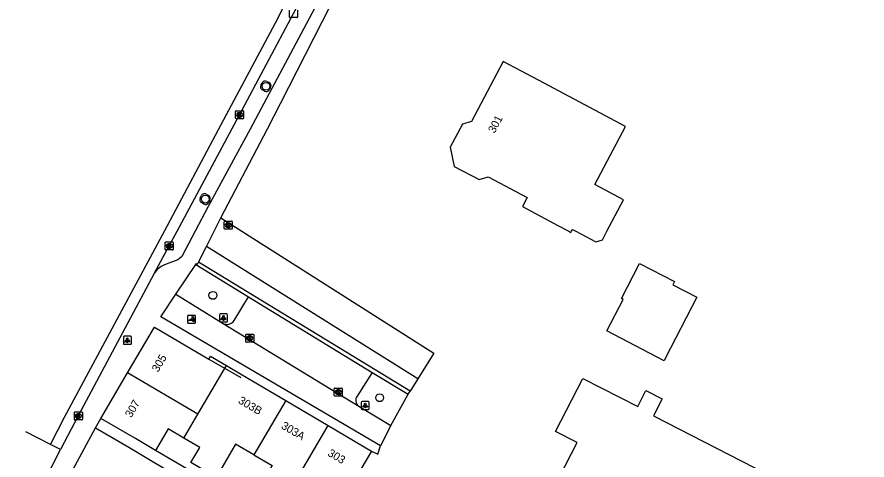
# Model space of a CAD drawing. Extents: x 160158 to 160921, y 381517 to 382041.
# Drawn here: x 160220.2 to 160326.4, y 381721.4 to 381776.8 of the extents above; entities that cross this region are included whole.
import ezdxf

# ---------------------------------------------------------------- set-up
doc = ezdxf.new("R2010")
doc.units = 0
for name, color, linetype in [('IMGEO_Boom', 7, 'Continuous'), ('IMGEO_Groenvoorziening', 7, 'Continuous'), ('IMGEO_Haag', 7, 'Continuous'), ('IMGEO_Kolk', 7, 'Continuous'), ('IMGEO_Lichtpunt', 7, 'Continuous'), ('IMGEO_Muur', 7, 'Continuous'), ('IMGEO_Pand', 7, 'Continuous'), ('IMGEO_Pand_nummerreeks', 7, 'Continuous'), ('IMGEO_Parkeervlak_halfverhard', 7, 'Continuous'), ('IMGEO_Parkeervlak_open', 7, 'Continuous'), ('IMGEO_Poller', 7, 'Continuous'), ('IMGEO_Rijbaan_lokaal_gesloten', 7, 'Continuous'), ('IMGEO_Rijbaan_lokaal_open', 7, 'Continuous'), ('IMGEO_Voetpad_open', 7, 'Continuous')]:
    doc.layers.add(name, color=color, linetype=linetype)

msp = doc.modelspace()

# ---------------------------------------------------------------- linework, layer by layer
at = {"layer": 'IMGEO_Boom'}
for centre in [(160251.32, 381768.11), (160243.74, 381754.01), (160244.69, 381741.97), (160265.53, 381729.18)]:
    msp.add_circle(centre, 0.489, dxfattribs=at)
at = {"layer": 'IMGEO_Groenvoorziening'}
msp.add_lwpolyline([(160266.92, 381725.7), (160269.08, 381729.64)], dxfattribs=at)
at = {"layer": 'IMGEO_Haag'}
for points in [[(160242.54, 381745.85), (160249.15, 381741.8)], [(160264.57, 381732.35), (160269.08, 381729.64)], [(160269.08, 381729.64), (160269.34, 381730.01)]]:
    msp.add_lwpolyline(points, dxfattribs=at)
at = {"layer": 'IMGEO_Kolk'}
for p, q in [((160254.24, 381776.77), (160254.24, 381777.63)), ((160255.17, 381776.7), (160254.32, 381776.7)), ((160255.24, 381777.63), (160255.24, 381776.77)), ((160247.52, 381764.12), (160247.52, 381764.97)), ((160247.59, 381765.04), (160248.45, 381765.04)), ((160248.52, 381764.97), (160248.52, 381764.12)), ((160248.45, 381764.04), (160247.59, 381764.04)), ((160248.01, 381764.82), (160248.03, 381764.82)), ((160248.03, 381764.26), (160248.01, 381764.26)), ((160246.11, 381750.32), (160246.11, 381751.18)), ((160246.19, 381751.25), (160247.04, 381751.25)), ((160247.11, 381751.18), (160247.11, 381750.32)), ((160247.04, 381750.25), (160246.19, 381750.25)), ((160246.6, 381751.03), (160246.63, 381751.03)), ((160246.62, 381750.47), (160246.6, 381750.47)), ((160238.73, 381747.72), (160238.73, 381748.57)), ((160238.81, 381748.65), (160239.66, 381748.65)), ((160239.22, 381748.43), (160239.25, 381748.43)), ((160239.74, 381748.57), (160239.74, 381747.72)), ((160239.66, 381747.65), (160238.81, 381747.65)), ((160239.24, 381747.87), (160239.22, 381747.87)), ((160248.79, 381736.2), (160248.79, 381737.06)), ((160248.86, 381737.13), (160249.71, 381737.13)), ((160249.27, 381736.91), (160249.3, 381736.91)), ((160249.3, 381736.35), (160249.27, 381736.35)), ((160249.79, 381737.06), (160249.79, 381736.2)), ((160249.71, 381736.13), (160248.86, 381736.13)), ((160259.86, 381729.46), (160259.86, 381730.31)), ((160259.93, 381730.39), (160260.79, 381730.39)), ((160260.35, 381730.16), (160260.37, 381730.16)), ((160260.86, 381730.31), (160260.86, 381729.46)), ((160260.79, 381729.38), (160259.93, 381729.38)), ((160260.37, 381729.61), (160260.34, 381729.61)), ((160227.38, 381726.48), (160227.38, 381727.33)), ((160227.45, 381727.4), (160228.3, 381727.4)), ((160227.86, 381727.18), (160227.89, 381727.18)), ((160228.38, 381727.33), (160228.38, 381726.48)), ((160228.3, 381726.4), (160227.45, 381726.4)), ((160227.89, 381726.62), (160227.86, 381726.62))]:
    msp.add_line(p, q, dxfattribs=at)
for points in [[(160254.24, 381776.77), (160254.24, 381777.63)], [(160255.17, 381776.7), (160254.32, 381776.7)], [(160255.24, 381777.63), (160255.24, 381776.77)], [(160247.52, 381764.12), (160247.52, 381764.97)], [(160247.59, 381765.04), (160248.45, 381765.04)], [(160248.52, 381764.97), (160248.52, 381764.12)], [(160248.45, 381764.04), (160247.59, 381764.04)], [(160247.84, 381764.74), (160247.96, 381764.74), (160247.96, 381764.59), (160248.09, 381764.74), (160248.26, 381764.74), (160248.11, 381764.59), (160248.26, 381764.34), (160248.11, 381764.34), (160248.03, 381764.51), (160247.96, 381764.44), (160247.96, 381764.34), (160247.84, 381764.34), (160247.84, 381764.74)], [(160246.11, 381750.32), (160246.11, 381751.18)], [(160246.19, 381751.25), (160247.04, 381751.25)], [(160247.11, 381751.18), (160247.11, 381750.32)], [(160247.04, 381750.25), (160246.19, 381750.25)], [(160246.43, 381750.95), (160246.56, 381750.95), (160246.56, 381750.8), (160246.69, 381750.95), (160246.85, 381750.95), (160246.71, 381750.8), (160246.86, 381750.55), (160246.71, 381750.55), (160246.62, 381750.72), (160246.56, 381750.65), (160246.56, 381750.55), (160246.43, 381750.55), (160246.43, 381750.95)], [(160238.73, 381747.72), (160238.73, 381748.57)], [(160238.81, 381748.65), (160239.66, 381748.65)], [(160239.05, 381748.35), (160239.18, 381748.35), (160239.18, 381748.2), (160239.31, 381748.35), (160239.47, 381748.35), (160239.33, 381748.2), (160239.48, 381747.95), (160239.33, 381747.95), (160239.24, 381748.11), (160239.18, 381748.05), (160239.18, 381747.95), (160239.05, 381747.95), (160239.05, 381748.35)], [(160239.74, 381748.57), (160239.74, 381747.72)], [(160239.66, 381747.65), (160238.81, 381747.65)], [(160248.79, 381736.2), (160248.79, 381737.06)], [(160248.86, 381737.13), (160249.71, 381737.13)], [(160249.11, 381736.83), (160249.23, 381736.83), (160249.23, 381736.68), (160249.36, 381736.83), (160249.52, 381736.83), (160249.38, 381736.68), (160249.53, 381736.43), (160249.38, 381736.43), (160249.29, 381736.59), (160249.23, 381736.53), (160249.23, 381736.43), (160249.11, 381736.43), (160249.11, 381736.83)], [(160249.79, 381737.06), (160249.79, 381736.2)], [(160249.71, 381736.13), (160248.86, 381736.13)], [(160259.86, 381729.46), (160259.86, 381730.31)], [(160259.93, 381730.39), (160260.79, 381730.39)], [(160260.18, 381730.08), (160260.3, 381730.08), (160260.3, 381729.93), (160260.43, 381730.08), (160260.6, 381730.08), (160260.45, 381729.93), (160260.6, 381729.68), (160260.45, 381729.68), (160260.37, 381729.85), (160260.3, 381729.78), (160260.3, 381729.68), (160260.18, 381729.68), (160260.18, 381730.08)], [(160260.86, 381730.31), (160260.86, 381729.46)], [(160260.79, 381729.38), (160259.93, 381729.38)], [(160227.38, 381726.48), (160227.38, 381727.33)], [(160227.45, 381727.4), (160228.3, 381727.4)], [(160227.7, 381727.1), (160227.82, 381727.1), (160227.82, 381726.95), (160227.95, 381727.1), (160228.11, 381727.1), (160227.97, 381726.95), (160228.12, 381726.7), (160227.97, 381726.7), (160227.88, 381726.87), (160227.82, 381726.8), (160227.82, 381726.7), (160227.7, 381726.7), (160227.7, 381727.1)], [(160228.38, 381727.33), (160228.38, 381726.48)], [(160228.3, 381726.4), (160227.45, 381726.4)]]:
    msp.add_lwpolyline(points, dxfattribs=at)
for centre, start, end in [((160254.32, 381776.77), 181.552, 268.448), ((160254.32, 381776.77), 181.552, 268.448), ((160255.17, 381776.77), 271.552, 358.448), ((160255.17, 381776.77), 271.552, 358.448), ((160247.6, 381764.97), 91.552, 178.448), ((160247.6, 381764.97), 91.552, 178.448), ((160248.44, 381764.97), 1.552, 88.448), ((160248.44, 381764.97), 1.552, 88.448), ((160247.6, 381764.12), 181.552, 268.448), ((160247.6, 381764.12), 181.552, 268.448), ((160248.44, 381764.12), 271.552, 358.448), ((160248.44, 381764.12), 271.552, 358.448), ((160246.19, 381751.18), 91.552, 178.448), ((160246.19, 381751.18), 91.552, 178.448), ((160247.04, 381751.18), 1.552, 88.448), ((160247.04, 381751.18), 1.552, 88.448), ((160246.19, 381750.33), 181.552, 268.448), ((160246.19, 381750.33), 181.552, 268.448), ((160247.04, 381750.33), 271.552, 358.448), ((160247.04, 381750.33), 271.552, 358.448), ((160238.81, 381748.57), 91.552, 178.448), ((160238.81, 381748.57), 91.552, 178.448), ((160239.66, 381748.57), 1.552, 88.448), ((160239.66, 381748.57), 1.552, 88.448), ((160238.81, 381747.72), 181.552, 268.448), ((160238.81, 381747.72), 181.552, 268.448), ((160239.66, 381747.72), 271.552, 358.448), ((160239.66, 381747.72), 271.552, 358.448), ((160248.86, 381737.05), 91.552, 178.448), ((160248.86, 381737.05), 91.552, 178.448), ((160249.71, 381737.05), 1.552, 88.448), ((160249.71, 381737.05), 1.552, 88.448), ((160248.86, 381736.2), 181.552, 268.448), ((160248.86, 381736.2), 181.552, 268.448), ((160249.71, 381736.2), 271.552, 358.448), ((160249.71, 381736.2), 271.552, 358.448), ((160259.93, 381730.31), 91.552, 178.448), ((160259.93, 381730.31), 91.552, 178.448), ((160260.78, 381730.31), 1.552, 88.448), ((160260.78, 381730.31), 1.552, 88.448), ((160259.93, 381729.46), 181.552, 268.448), ((160259.93, 381729.46), 181.552, 268.448), ((160260.78, 381729.46), 271.552, 358.448), ((160260.78, 381729.46), 271.552, 358.448), ((160227.45, 381727.33), 91.552, 178.448), ((160227.45, 381727.33), 91.552, 178.448), ((160228.3, 381727.33), 1.552, 88.448), ((160228.3, 381727.33), 1.552, 88.448), ((160227.45, 381726.48), 181.552, 268.448), ((160227.45, 381726.48), 181.552, 268.448), ((160228.3, 381726.48), 271.552, 358.448), ((160228.3, 381726.48), 271.552, 358.448)]:
    msp.add_arc(centre, 0.0765, start, end, dxfattribs=at)
for centre, major_axis, ratio, start_param, end_param in [((160248.01, 381764.54), (-0.387, 0.002), 0.722429, 4.712389, 7.853982), ((160248.03, 381764.54), (-0.39, 0.002), 0.717154, 1.570796, 4.712389), ((160246.6, 381750.75), (-0.387, 0.002), 0.722429, 4.712389, 7.853982), ((160246.62, 381750.75), (-0.39, 0.002), 0.717154, 1.570796, 4.712389), ((160239.22, 381748.15), (-0.387, 0.002), 0.722429, 4.712389, 7.853982), ((160239.25, 381748.15), (-0.39, 0.002), 0.717154, 1.570796, 4.712389), ((160249.27, 381736.63), (-0.387, 0.002), 0.722429, 4.712389, 7.853982), ((160249.3, 381736.63), (-0.39, 0.002), 0.717154, 1.570796, 4.712389), ((160260.35, 381729.88), (-0.387, 0.002), 0.722429, 4.712389, 7.853982), ((160260.37, 381729.88), (-0.39, 0.002), 0.717154, 1.570796, 4.712389), ((160227.86, 381726.9), (-0.387, 0.002), 0.722429, 4.712389, 7.853982), ((160227.89, 381726.9), (-0.39, 0.002), 0.717154, 1.570796, 4.712389)]:
    msp.add_ellipse(centre, major_axis=major_axis, ratio=ratio, start_param=start_param, end_param=end_param, dxfattribs=at)
at = {"layer": 'IMGEO_Lichtpunt'}
for p, q in [((160245.51, 381739.56), (160245.51, 381738.75)), ((160245.51, 381739.56), (160245.51, 381738.75)), ((160246.41, 381739.66), (160245.61, 381739.66)), ((160246.41, 381739.66), (160245.61, 381739.66)), ((160246.51, 381738.75), (160246.51, 381739.56)), ((160246.51, 381738.75), (160246.51, 381739.56)), ((160245.61, 381738.66), (160246.41, 381738.66)), ((160245.61, 381738.66), (160246.41, 381738.66)), ((160233.51, 381736.76), (160233.51, 381735.96)), ((160233.51, 381736.76), (160233.51, 381735.96)), ((160234.41, 381736.86), (160233.6, 381736.86)), ((160234.41, 381736.86), (160233.6, 381736.86)), ((160234.51, 381735.96), (160234.51, 381736.76)), ((160234.51, 381735.96), (160234.51, 381736.76)), ((160233.6, 381735.86), (160234.41, 381735.86)), ((160233.6, 381735.86), (160234.41, 381735.86)), ((160263.22, 381728.6), (160263.22, 381727.8)), ((160263.22, 381728.6), (160263.22, 381727.8)), ((160264.12, 381728.7), (160263.32, 381728.7)), ((160264.12, 381728.7), (160263.32, 381728.7)), ((160264.22, 381727.8), (160264.22, 381728.6)), ((160264.22, 381727.8), (160264.22, 381728.6)), ((160263.32, 381727.7), (160264.12, 381727.7)), ((160263.32, 381727.7), (160264.12, 381727.7))]:
    msp.add_line(p, q, dxfattribs=at)
for points in [[(160245.89, 381739.22), (160245.92, 381739.2), (160245.74, 381738.93), (160245.7, 381738.96), (160245.89, 381739.22)], [(160245.99, 381739.18), (160246.04, 381739.18), (160246.04, 381738.85), (160245.99, 381738.85), (160245.99, 381739.18)], [(160246.1, 381739.2), (160246.14, 381739.22), (160246.32, 381738.96), (160246.28, 381738.93), (160246.1, 381739.2)], [(160233.88, 381736.43), (160233.92, 381736.4), (160233.73, 381736.14), (160233.7, 381736.16), (160233.88, 381736.43)], [(160233.98, 381736.38), (160234.03, 381736.38), (160234.03, 381736.06), (160233.98, 381736.06), (160233.98, 381736.38)], [(160234.09, 381736.4), (160234.13, 381736.43), (160234.32, 381736.16), (160234.28, 381736.14), (160234.09, 381736.4)], [(160263.6, 381728.27), (160263.63, 381728.24), (160263.45, 381727.98), (160263.41, 381728), (160263.6, 381728.27)], [(160263.7, 381728.22), (160263.74, 381728.22), (160263.74, 381727.9), (160263.7, 381727.9), (160263.7, 381728.22)], [(160263.81, 381728.24), (160263.85, 381728.27), (160264.03, 381728), (160263.99, 381727.98), (160263.81, 381728.24)]]:
    msp.add_lwpolyline(points, dxfattribs=at)
for centre in [(160246.01, 381739.36), (160234.01, 381736.56), (160263.72, 381728.4)]:
    msp.add_circle(centre, 0.0994, dxfattribs=at)
for centre, start, end in [((160245.61, 381739.56), 90, 180), ((160245.61, 381739.56), 90, 180), ((160246.41, 381739.56), 0, 90), ((160246.41, 381739.56), 0, 90), ((160245.61, 381738.75), 180, 270), ((160245.61, 381738.75), 180, 270), ((160246.41, 381738.75), 270, 0), ((160246.41, 381738.75), 270, 360), ((160233.6, 381736.76), 90, 180), ((160233.6, 381736.76), 90, 180), ((160234.41, 381736.76), 0, 90), ((160234.41, 381736.76), 0, 90), ((160233.6, 381735.96), 180, 270), ((160233.6, 381735.96), 180, 270), ((160234.41, 381735.96), 270, 0), ((160234.41, 381735.96), 270, 360), ((160263.32, 381728.6), 90, 180), ((160263.32, 381728.6), 90, 180), ((160263.32, 381727.8), 180, 270), ((160263.32, 381727.8), 180, 270), ((160264.12, 381728.6), 0, 90), ((160264.12, 381728.6), 0, 90), ((160264.12, 381727.8), 270, 0), ((160264.12, 381727.8), 270, 360)]:
    msp.add_arc(centre, 0.0946, start, end, dxfattribs=at)
at = {"layer": 'IMGEO_Muur'}
for points in [[(160253.12, 381765.96), (160265.61, 381790.49), (160266.77, 381793.11)], [(160245.7, 381751.66), (160251.51, 381762.79)], [(160242.91, 381746.14), (160243.9, 381748.1)], [(160244.17, 381734.01), (160248.16, 381731.69)]]:
    msp.add_lwpolyline(points, dxfattribs=at)
at = {"layer": 'IMGEO_Pand'}
for points in [[(160285.39, 381768.86), (160280.97, 381771.21), (160276.99, 381763.71), (160275.86, 381763.36), (160274.35, 381760.5), (160274.84, 381758.1), (160277.95, 381756.46), (160279.1, 381756.81), (160283.97, 381754.23), (160283.36, 381753.07), (160287.77, 381750.73), (160289.15, 381750), (160289.42, 381749.85), (160289.5, 381750), (160289.62, 381750.22), (160290.04, 381750), (160292.55, 381748.67), (160293.35, 381748.91), (160293.92, 381750), (160296, 381753.91), (160292.4, 381755.82), (160296.26, 381763.1), (160285.39, 381768.86)], [(160301.21, 381734.09), (160301.07, 381733.81), (160293.93, 381737.53), (160295.95, 381741.46), (160295.73, 381741.58), (160297.98, 381745.98), (160302.38, 381743.72), (160302.15, 381743.28), (160305.14, 381741.74), (160301.21, 381734.09)], [(160234.03, 381732.29), (160237.38, 381737.99), (160244.17, 381734.01), (160244.38, 381734.37), (160246.37, 381733.2)], [(160242.82, 381727.14), (160244.58, 381730.16), (160246.37, 381733.2)], [(160246.37, 381733.2), (160248.36, 381732.03), (160253.8, 381728.83)], [(160230.69, 381726.6), (160234.03, 381732.29)], [(160242.82, 381727.14), (160234.03, 381732.29)], [(160280.33, 381704.38), (160290.19, 381723.57), (160287.51, 381724.95), (160290.93, 381731.6), (160297.77, 381728.09), (160298.79, 381730.08), (160300.82, 381729.04), (160299.73, 381726.91), (160326.42, 381713.21)], [(160253.8, 381728.83), (160249.82, 381722.03)], [(160253.8, 381728.83), (160259.08, 381725.71)], [(160241.05, 381724.13), (160242.82, 381727.14)], [(160237.5, 381722.6), (160235, 381724.07), (160230.69, 381726.6)], [(160252.67, 381714.77), (160259.08, 381725.71)], [(160259.08, 381725.71), (160264.51, 381722.52)], [(160226.06, 381718.08), (160230.04, 381725.41)], [(160230.04, 381725.41), (160234.18, 381722.99), (160236.9, 381721.39), (160246.06, 381715.93), (160245.89, 381715.64)], [(160241.05, 381724.13), (160239.08, 381725.28), (160237.5, 381722.6)], [(160249.82, 381722.03), (160247.53, 381723.38), (160245.09, 381719.22), (160241.94, 381721.07), (160243.04, 381722.96), (160241.05, 381724.13)], [(160264.51, 381722.52), (160261.97, 381718.21), (160260.49, 381715.69), (160258.08, 381717.11), (160255.73, 381712.97), (160252.67, 381714.77)], [(160249.82, 381722.03), (160252.11, 381720.69), (160249.67, 381716.52), (160252.67, 381714.77)]]:
    msp.add_lwpolyline(points, dxfattribs=at)
at = {"layer": 'IMGEO_Parkeervlak_halfverhard'}
for points in [[(160269.34, 381730.01), (160242.91, 381746.14)], [(160270.28, 381731.55), (160269.34, 381730.01)]]:
    msp.add_lwpolyline(points, dxfattribs=at)
at = {"layer": 'IMGEO_Parkeervlak_open'}
for points in [[(160250.68, 381768.24), (160250.85, 381768.54)], [(160251.43, 381768.71), (160251.71, 381768.59)], [(160251.15, 381767.51), (160250.89, 381767.67)], [(160251.89, 381767.98), (160251.76, 381767.7)], [(160243.11, 381754.18), (160243.23, 381754.43)], [(160243.87, 381754.62), (160244.13, 381754.48)], [(160243.53, 381753.4), (160243.29, 381753.56)], [(160244.29, 381753.87), (160244.18, 381753.59)], [(160247.33, 381738.83), (160249.15, 381741.8)], [(160249.15, 381741.8), (160264.57, 381732.35)], [(160264.57, 381732.35), (160262.72, 381729.38)]]:
    msp.add_lwpolyline(points, dxfattribs=at)
for centre, radius, start, end in [((160251.04, 381768.05), 0.409, 151.2306, 247.837), ((160251.23, 381768.33), 0.434, 61.8607, 150.6522), ((160251.53, 381768.21), 0.424, 327.8477, 64.6148), ((160251.36, 381767.89), 0.435, 240.0897, 334.6825), ((160243.64, 381754.23), 0.457, 60.0971, 152.887), ((160243.94, 381754.1), 0.424, 326.8178, 62.9281), ((160243.51, 381753.97), 0.457, 151.9122, 241.9281), ((160243.77, 381753.8), 0.464, 239.6074, 333.0759), ((160246.47, 381739.36), 1.01, 241.4205, 328.3359), ((160263.4, 381728.85), 0.864, 141.9001, 235.6958)]:
    msp.add_arc(centre, radius, start, end, dxfattribs=at)
at = {"layer": 'IMGEO_Poller'}
for p, q in [((160242.42, 381739.47), (160241.61, 381739.47)), ((160242.42, 381739.47), (160241.61, 381739.47)), ((160241.52, 381739.38), (160241.52, 381738.57)), ((160241.52, 381739.38), (160241.52, 381738.57)), ((160241.61, 381738.48), (160242.42, 381738.48)), ((160241.61, 381738.48), (160242.42, 381738.48)), ((160242.51, 381738.57), (160242.51, 381739.38)), ((160242.51, 381738.57), (160242.51, 381739.38))]:
    msp.add_line(p, q, dxfattribs=at)
for points in [[(160242.15, 381738.83), (160241.64, 381738.83), (160242.07, 381739.1)], [(160242.2, 381739.2), (160242.18, 381739.13), (160242.06, 381739.33)], [(160242.06, 381739.33), (160242.29, 381739.27), (160242.22, 381739.24)], [(160242.21, 381738.66), (160242.28, 381738.89), (160242.31, 381738.82)], [(160242.35, 381738.79), (160242.42, 381738.78), (160242.21, 381738.66)]]:
    msp.add_lwpolyline(points, dxfattribs=at)
for centre, radius, start, end in [((160241.61, 381739.38), 0.0946, 90, 180), ((160241.61, 381739.38), 0.0946, 90, 180), ((160242.42, 381739.38), 0.0946, 0, 90), ((160242.42, 381739.38), 0.0946, 0, 90), ((160241.61, 381738.57), 0.0946, 180, 270), ((160241.61, 381738.57), 0.0946, 180, 270), ((160241.82, 381738.88), 0.332, 351.3247, 42.4854), ((160241.84, 381738.89), 0.476, 351.7527, 41.1691), ((160241.84, 381738.89), 0.516, 349.3569, 42.2912), ((160242.42, 381738.57), 0.0946, 270, 0), ((160242.42, 381738.57), 0.0946, 270, 0)]:
    msp.add_arc(centre, radius, start, end, dxfattribs=at)
at = {"layer": 'IMGEO_Rijbaan_lokaal_gesloten'}
for points in [[(160224.38, 381723.35), (160226.13, 381726.77), (160238.68, 381750.08), (160245.71, 381763.32), (160252.51, 381776.06), (160256.59, 381784.17), (160259.85, 381791.2), (160263.48, 381799.77), (160268.78, 381814.05), (160271.36, 381822.03), (160273.77, 381830.38), (160275.32, 381836.47)], [(160237.37, 381744.72), (160239.23, 381748.15), (160240.22, 381750), (160248.02, 381764.54), (160254.74, 381777.2), (160257.05, 381781.79)], [(160243.9, 381748.1), (160245.7, 381751.66)], [(160245.7, 381751.66), (160272.31, 381734.74), (160270.28, 381731.55)], [(160270.28, 381731.55), (160243.9, 381748.1)], [(160237.37, 381744.72), (160234.08, 381738.56), (160227.87, 381726.9), (160225.65, 381722.7)]]:
    msp.add_lwpolyline(points, dxfattribs=at)
at = {"layer": 'IMGEO_Rijbaan_lokaal_open'}
for points in [[(160265.65, 381723.16), (160238.18, 381739.31), (160240.05, 381742.14)], [(160240.05, 381742.14), (160245.99, 381738.47)], [(160245.99, 381738.47), (160262.91, 381728.14)], [(160262.91, 381728.14), (160266.92, 381725.7)], [(160266.92, 381725.7), (160265.65, 381723.16)], [(160224.38, 381723.35), (160221.32, 381724.92)], [(160220.21, 381711.98), (160225.65, 381722.7)], [(160225.65, 381722.7), (160224.38, 381723.35)]]:
    msp.add_lwpolyline(points, dxfattribs=at)
at = {"layer": 'IMGEO_Voetpad_open'}
for points in [[(160245.7, 381751.66), (160251.51, 381762.79), (160253.12, 381765.96), (160265.61, 381790.49), (160266.77, 381793.11), (160268.19, 381796.46), (160270.9, 381802.95)], [(160257.38, 381777.83), (160251.73, 381767.2), (160249.34, 381762.75), (160244.11, 381753.07), (160242.48, 381750), (160240.79, 381746.84), (160240.52, 381746.57), (160240.32, 381746.41), (160238.86, 381745.87), (160238.57, 381745.76)], [(160242.91, 381746.14), (160243.9, 381748.1)], [(160240.05, 381742.14), (160242.54, 381745.85)], [(160242.54, 381745.85), (160242.62, 381745.95), (160242.75, 381745.86), (160242.91, 381746.14)], [(160230.04, 381725.41), (160230.69, 381726.6)], [(160250.96, 381712.54), (160251.95, 381714.12), (160237.5, 381722.6)], [(160264.51, 381722.52), (160265.28, 381722.13), (160265.65, 381723.16)]]:
    msp.add_lwpolyline(points, dxfattribs=at)
msp.add_arc((160239.55, 381743.43), 2.53, 112.7806, 149.2921, dxfattribs=at)

# ---------------------------------------------------------------- texts
at = {"layer": 'IMGEO_Pand_nummerreeks'}
for s, rotation, p in [('301', 62.0676, (160279.89, 381762.17)), ('305', 59.5819, (160237.84, 381732.3)), ('307', 59.5813, (160234.49, 381726.6)), ('303B', 329.4957, (160247.77, 381728.57)), ('303A', 329.4913, (160253.13, 381725.41)), ('303', 329.498, (160258.94, 381721.99))]:
    msp.add_text(s, height=1, rotation=rotation, dxfattribs=at).set_placement(p)

doc.saveas('drawing.dxf')
